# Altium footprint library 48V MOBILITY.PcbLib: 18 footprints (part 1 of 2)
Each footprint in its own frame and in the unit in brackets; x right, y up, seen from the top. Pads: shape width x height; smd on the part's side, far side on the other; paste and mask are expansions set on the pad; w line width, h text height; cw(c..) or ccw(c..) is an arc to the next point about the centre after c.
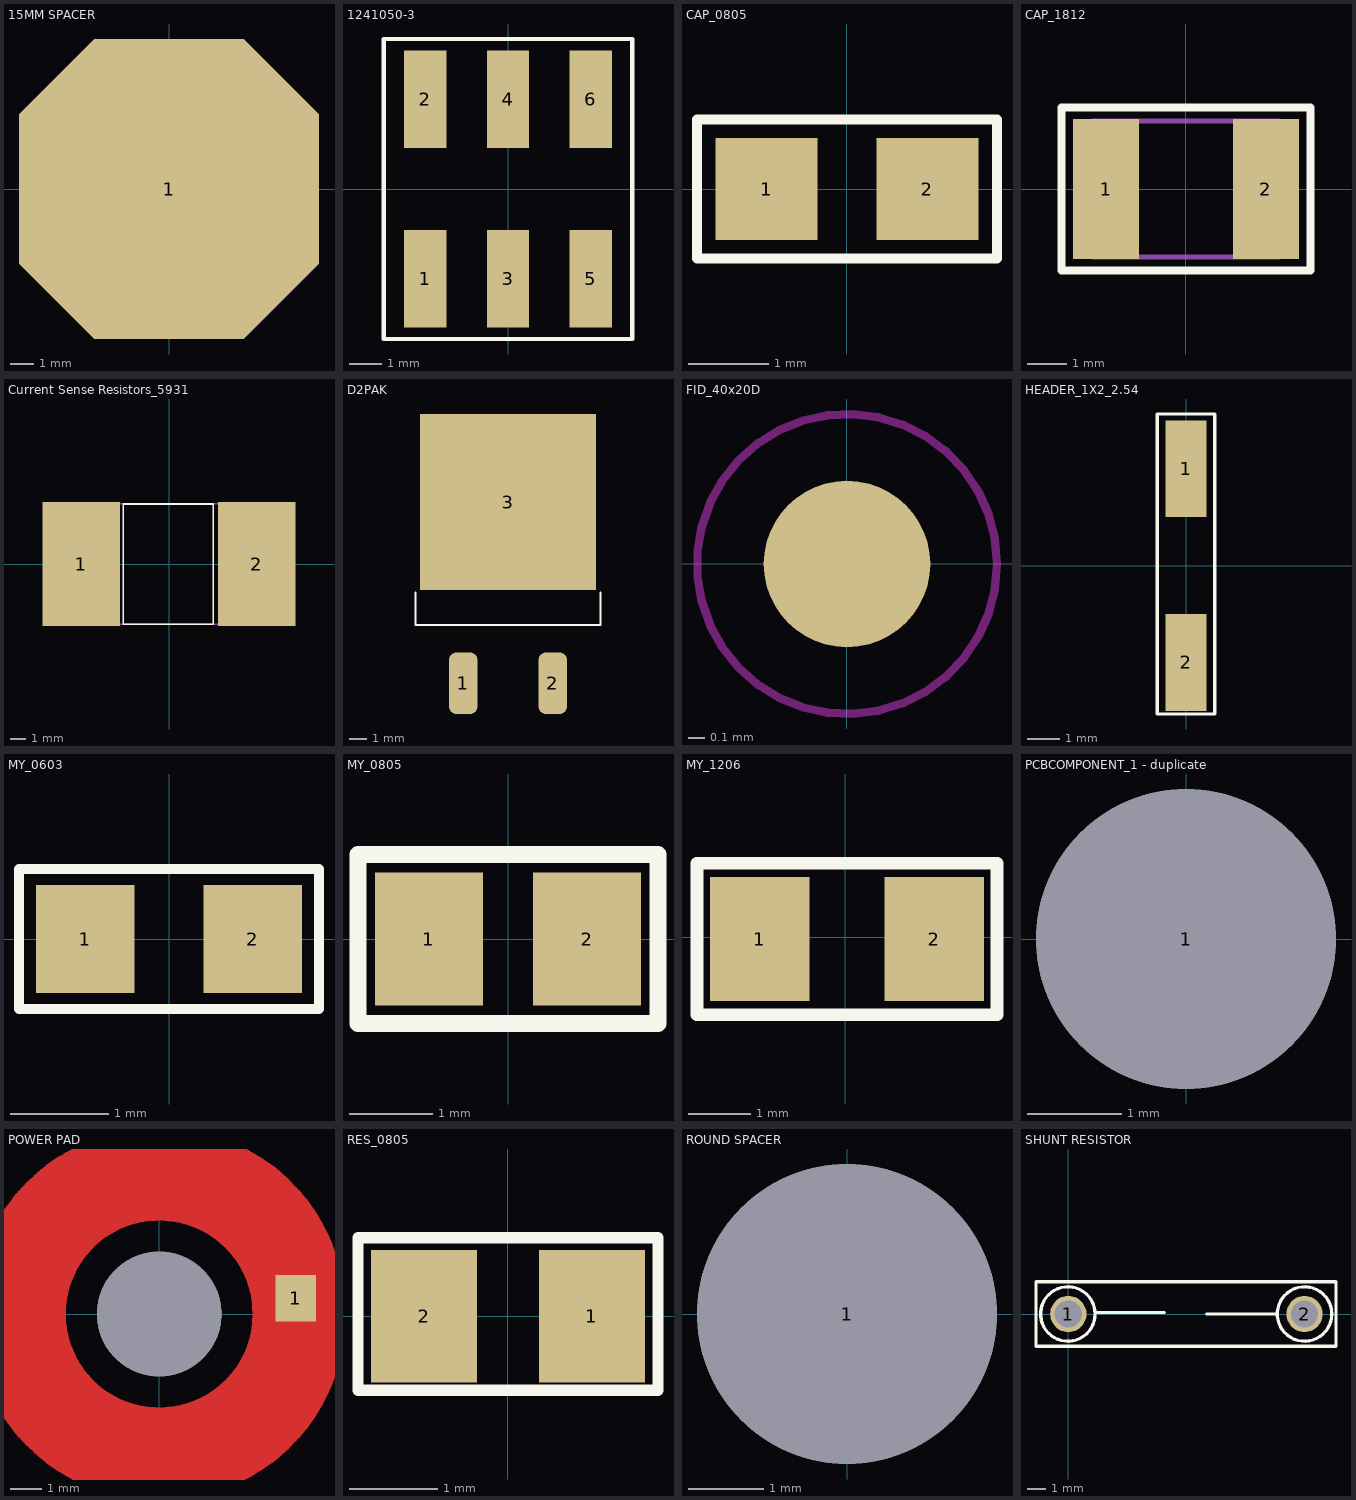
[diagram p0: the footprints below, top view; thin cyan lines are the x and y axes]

## 15MM SPACER [mm]
pads (1):
  oct 13x13 smd: 1(0,0)
3D body "Download_STEP_963150174 (rev1).stp": height 15.2, standoff 0.2, extent -4,-3.997 4,3.997

## 1241050-3 [mm] "1241050-3"
pads (6):
  rect 1.3x3 smd: 1(-2.54,-2.754) 2(-2.54,2.754) 3(0,-2.754) 4(0,2.754) 5(2.54,-2.754) 6(2.54,2.754)
Top Overlay:
  pour cut-out: -3.81,4.318
  lines w0.125: -3.81,-4.6 -3.81,4.6 3.81,4.6 3.81,-4.6 -3.81,-4.6
3D body "61030621121 (rev1).stp": height 9.57, standoff -0.03, extent -3.81,-3.75 3.81,3.75

## CAP_0805 [mm] "Ceramic Capacitor"
height 0.7
pads (2):
  rect 1.27x1.27 smd mask+0.076: 1(-1,0) 2(1,0)
Top Overlay:
  lines w0.127: 1.845,-0.864 -0.289,-0.864 -1.864,-0.864 -1.864,0.864 0.27,0.864 1.845,0.864 ; 1.864,-0.864 1.864,0.864
3D body "0805 SMD Capacitor.STEP": height 0.78, standoff 0, extent -1,-0.625 1,0.625

## CAP_1812 [mm] "CAP_1812"
pads (2):
  rect 1.7x3.6 smd: 1(-2.057,0) 2(2.057,0)
Top Overlay:
  lines w0.203: -3.2,-2.1 -3.2,2.1 3.2,2.1 3.2,-2.1 -3.2,-2.1
Mechanical 13:
  lines w0.127: -2.4,-1.75 2.4,-1.75 2.4,1.75 -2.4,1.75 -2.4,-1.75
3D body "step_temp.STEP": height 1.1, standoff 0, extent -2.25,-1.6 2.25,1.6

## Current Sense Resistors_5931 [mm]
pads (2):
  rect 5x8 smd: 1(-5.65,0) 2(5.65,0)
Top Overlay:
  lines w0.1: -2.946,-3.886 -2.946,3.861 2.845,3.861 2.845,-3.886 -2.946,-3.886
Mechanical 13:
  lines w0.1: -7.5,-3.875 -7.5,3.875 7.5,3.875 7.5,-3.875 -7.5,-3.875
3D body "PU5931FKNT50U5L.stp": height 1.13, standoff 0, extent -7.5,-3.875 7.5,3.875

## D2PAK [mm]
pads (3):
  rrect50% 1.6x3.5 smd: 1(30.861,-125.152) 2(35.941,-125.152)
  rect 10x10 smd paste-7: 3(33.401,-114.877)
Top Overlay:
  lines w0.127: 28.151,-120.002 28.151,-121.852 38.651,-121.852 38.651,-120.002
Top Paste:
  region: 33.106,-111.232 33.106,-112.603 31.636,-112.603 31.636,-111.232
  region: 35.167,-111.232 35.167,-112.609 33.696,-112.609 33.696,-111.232
  region: 35.168,-113.202 35.168,-114.578 33.696,-114.578 33.696,-113.202
  region: 33.106,-113.202 33.106,-114.576 31.636,-114.576 31.636,-113.202
  region: 31.039,-113.202 31.039,-114.578 29.571,-114.578 29.571,-113.202
  region: 31.039,-111.232 31.039,-112.608 29.571,-112.608 29.571,-111.232
  region: 37.237,-113.202 37.237,-114.576 35.761,-114.576 35.761,-113.202
  region: 37.238,-111.232 37.238,-112.602 35.761,-112.602 35.761,-111.232
  region: 35.168,-117.142 35.168,-118.523 33.696,-118.523 33.696,-117.142
  region: 33.105,-117.142 33.105,-118.523 31.636,-118.523 31.636,-117.142
  region: 33.106,-115.172 33.106,-116.55 31.636,-116.55 31.636,-115.172
  region: 35.167,-115.172 35.167,-116.551 33.696,-116.551 33.696,-115.172
  region: 37.236,-115.172 37.236,-116.55 35.761,-116.55 35.761,-115.172
  region: 37.235,-117.142 37.235,-118.523 35.761,-118.523 35.761,-117.142
  region: 31.039,-115.172 31.039,-116.551 29.571,-116.551 29.571,-115.172
  region: 31.039,-117.142 31.039,-118.523 29.571,-118.523 29.571,-117.142
Mechanical 13:
  lines w0.127: 28.401,-121.852 38.401,-121.852
3D body "Infineon-STP_PG-TO263-3-2-P-v01_00-EN.stp": height 4.51, standoff 0, extent 28.401,-124.968 38.401,-110.018

## FID_40x20D [mm]
pads (1):
  round 1 smd mask+0: ""(0,0)
Top Solder:
  circle w0.9: c0,0 r0.45
Keep-Out Layer:
  circle w0.05: c0,0 r0.9

## HEADER_1X2_2.54 [mm] "HEADER_2X2_2.54"
pads (2):
  rect 1.27x3 smd: 1(0,3) 2(0,-3)
Top Overlay:
  lines w0.1: -0.889,-4.6 0.889,-4.6 0.889,4.7 -0.889,4.7 -0.889,-4.6

## MY_0603 [mm]
pads (2):
  rect 1x1.1 smd: 1(-0.85,0) 2(0.85,0)
Top Overlay:
  lines w0.102: -1.524,-0.711 1.524,-0.711 1.524,0.711 -1.524,0.711 -1.524,-0.711
3D body "User Library-SMD RESISTOR-1.STEP": height 0.44, standoff -0.01, extent -0.8,-0.4 0.8,0.4

## MY_0805 [mm]
height 0.038
pads (2):
  rect 1.3x1.6 smd: 1(-0.95,0) 2(0.95,0)
Top Overlay:
  lines w0.203: -1.803,-1.016 1.803,-1.016 1.803,1.016 -1.803,1.016 -1.803,-1.016
3D body "User Library-SMD RESISTOR-1.STEP": height 0.59, standoff -0.01, extent -1,-0.625 1,0.625

## MY_1206 [mm]
height 0.051
pads (2):
  rect 1.6x2 smd: 1(-1.375,-0.025) 2(1.425,-0.025)
Top Overlay:
  lines w0.203: -2.388,-1.245 2.438,-1.245 2.438,1.194 -2.388,1.194 -2.388,-1.245
3D body "User Library-SMD RESISTOR-1.STEP": height 0.59, standoff -0.01, extent -1.575,-0.825 1.625,0.775

## PCBCOMPONENT_1 - duplicate [mm]
pads (1):
  round 3.2 hole 3.2: 1(0,0)

## POWER PAD [mm]
pads (2):
  rect 1.3x1.5 smd mask+0.076: 1(4.379,0.508)
  round 4 hole 4 unplated: ""(0,0)
Top Layer:
  circle w3: c0,0 r4.5

## RES_0805 [mm] "Resister"
height 0.65
pads (2):
  rect 1.2x1.5 smd mask+0.076: 1(0.95,0) 2(-0.95,0)
Top Overlay:
  lines w0.127: -1.7,-0.838 1.7,-0.838 1.7,0.889 -1.7,0.889 -1.7,-0.838
3D body "RES0805.stp": height 0.5, standoff 0, extent -1,-0.63 1,0.62

## ROUND SPACER [mm]
pads (1):
  round 4 hole 4: 1(0,0)

## SHUNT RESISTOR [mm] "NA"
height 41
pads (2):
  round 2 hole 1.5: 1(0,0) 2(13,0)
Top Overlay:
  circle w0.178: c-0.025,0 r1.5
  circle w0.178: c13,0 r1.5
  lines w0.178: 1.473,0.076 5.283,0.076 ; 7.62,0 11.43,0 ; -1.778,-1.778 -1.778,1.778 14.732,1.778 14.732,-1.778 -1.778,-1.778
3D body: height 4.57, standoff 3.05, extent -0.762,-0.747 0.754,0.77
3D body: height 4.57, standoff 3.05, extent 12.246,-0.759 13.762,0.759
3D body: height 3.81, standoff -2.54, extent 12.244,-0.76 13.762,0.761
3D body: height 3.81, standoff -2.54, extent -0.762,-0.749 0.756,0.772
3D body: height 4.57, standoff 3.05, extent -0.277,-0.629 12.723,0.889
